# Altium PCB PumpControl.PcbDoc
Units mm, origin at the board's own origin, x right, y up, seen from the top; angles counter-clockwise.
Board outline 52.07 x 92.61 mm, 2 copper layers (Top Layer, Bottom Layer); 86 components, 56 nets, 282 pads, 79 vias.
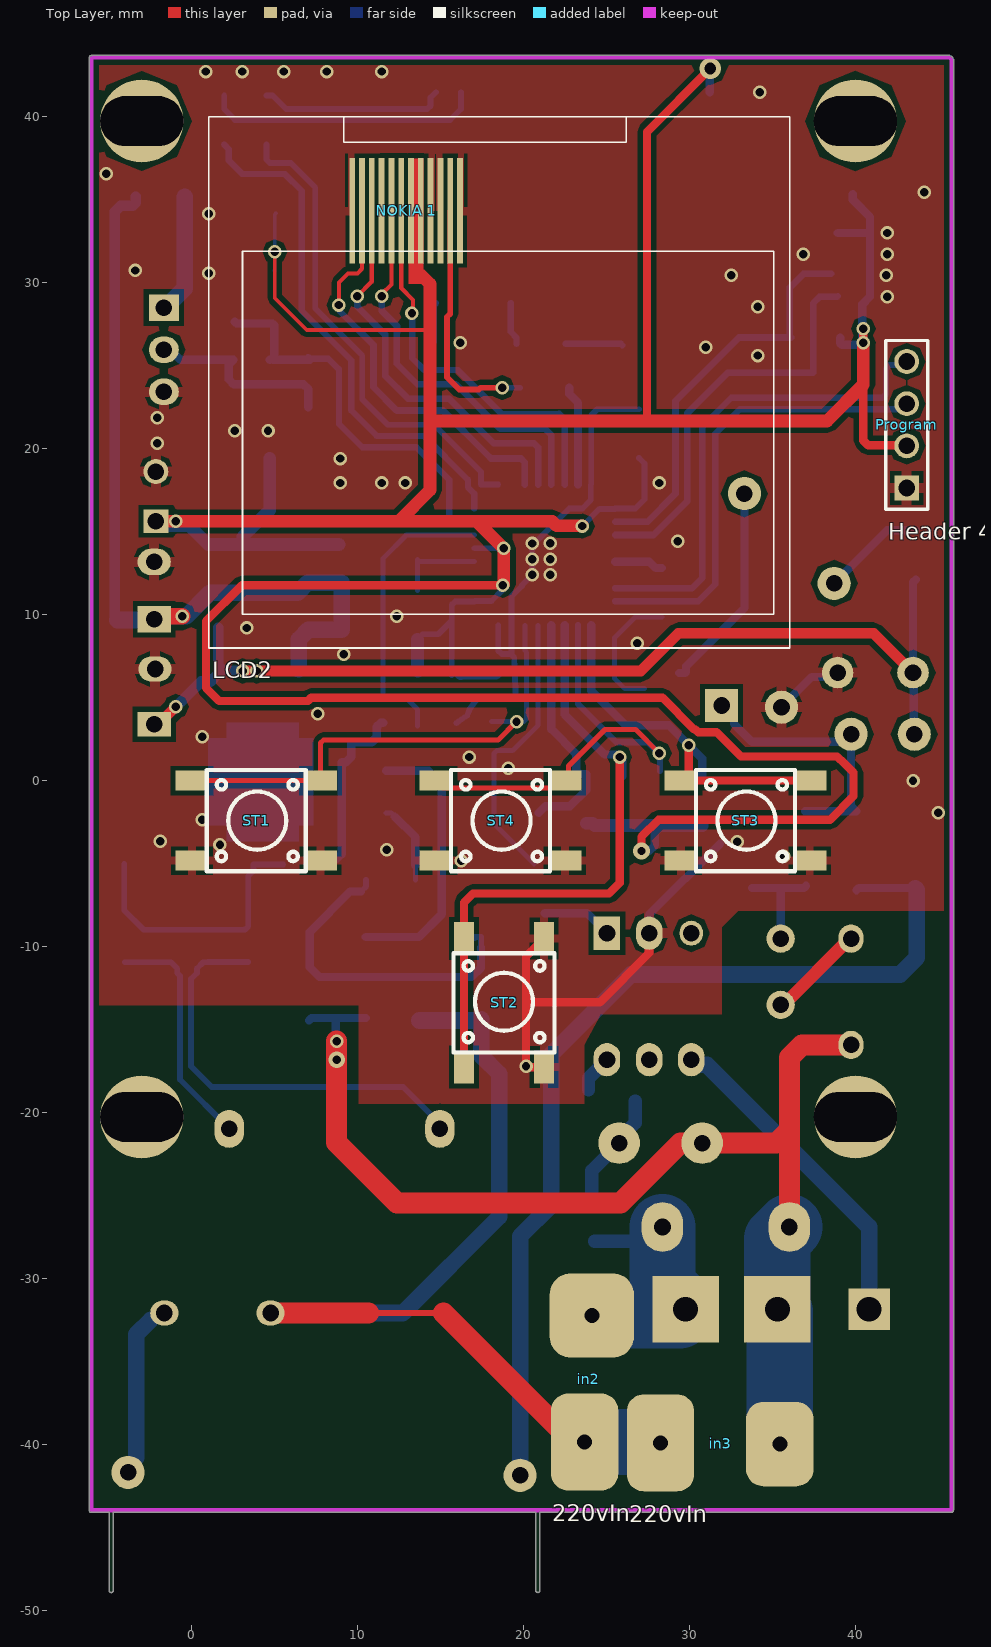
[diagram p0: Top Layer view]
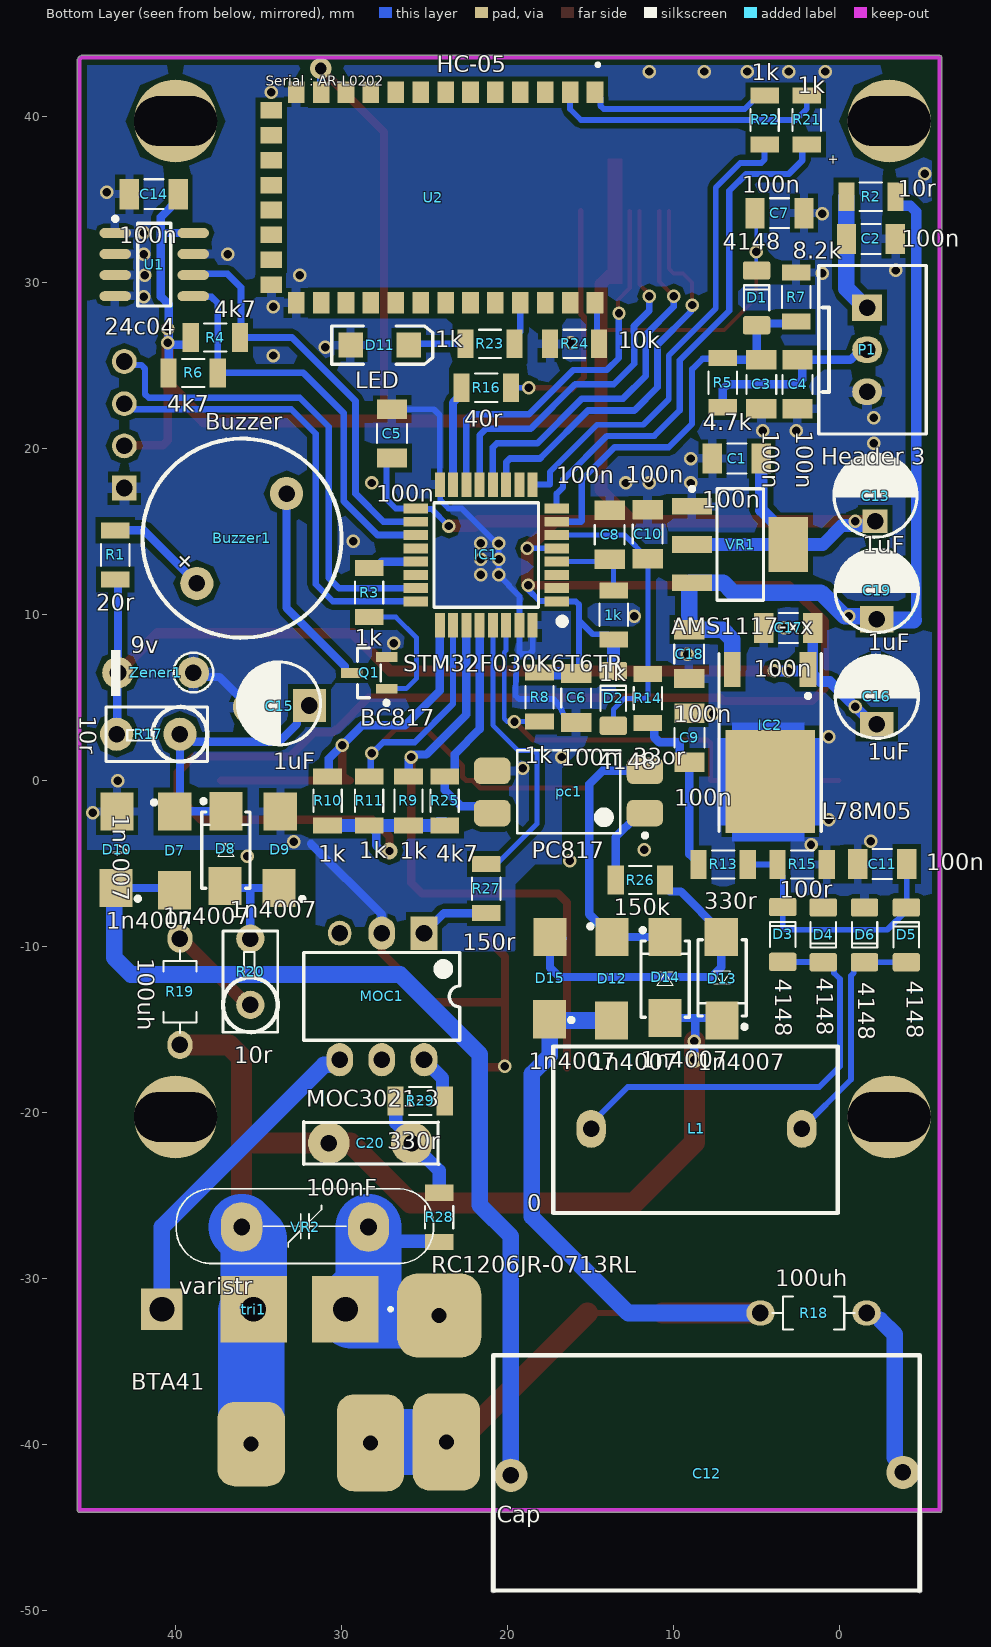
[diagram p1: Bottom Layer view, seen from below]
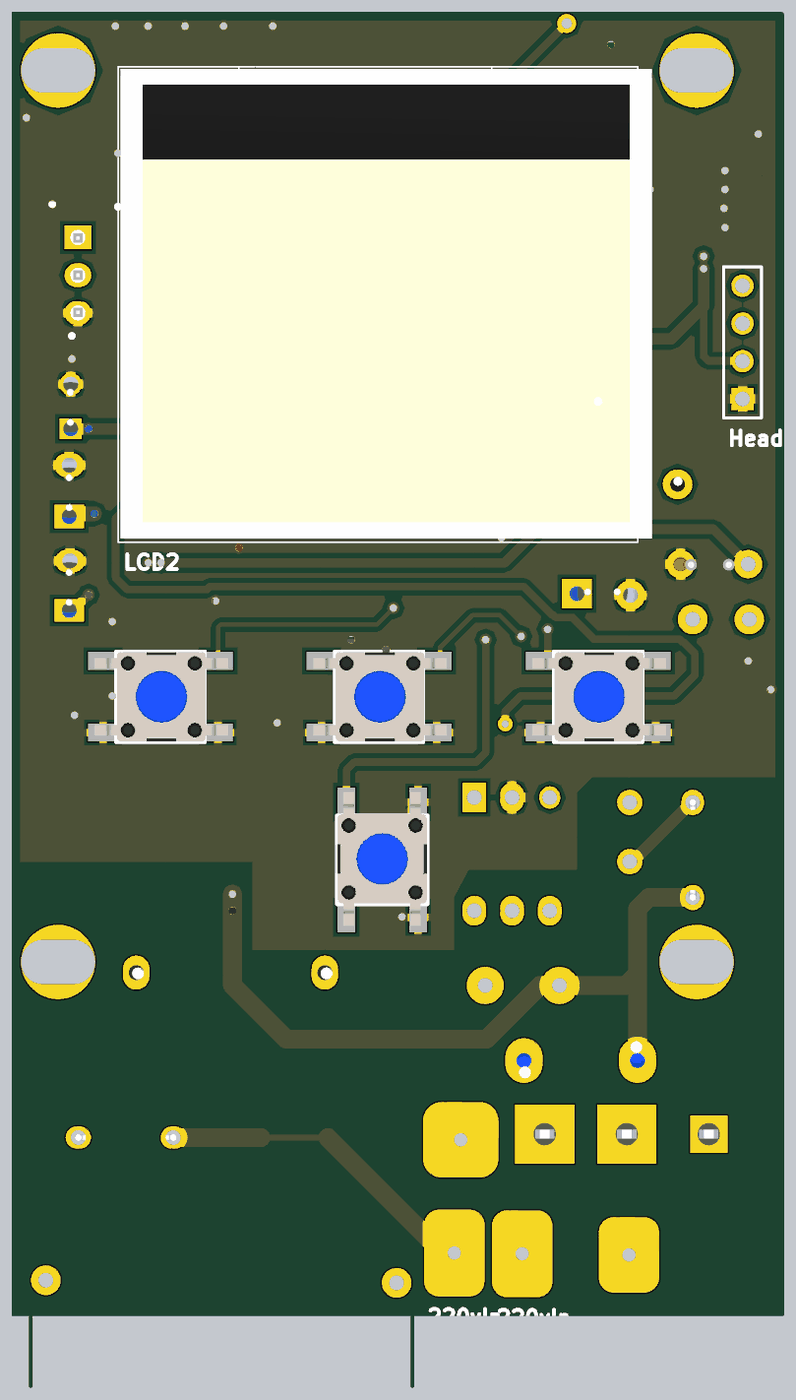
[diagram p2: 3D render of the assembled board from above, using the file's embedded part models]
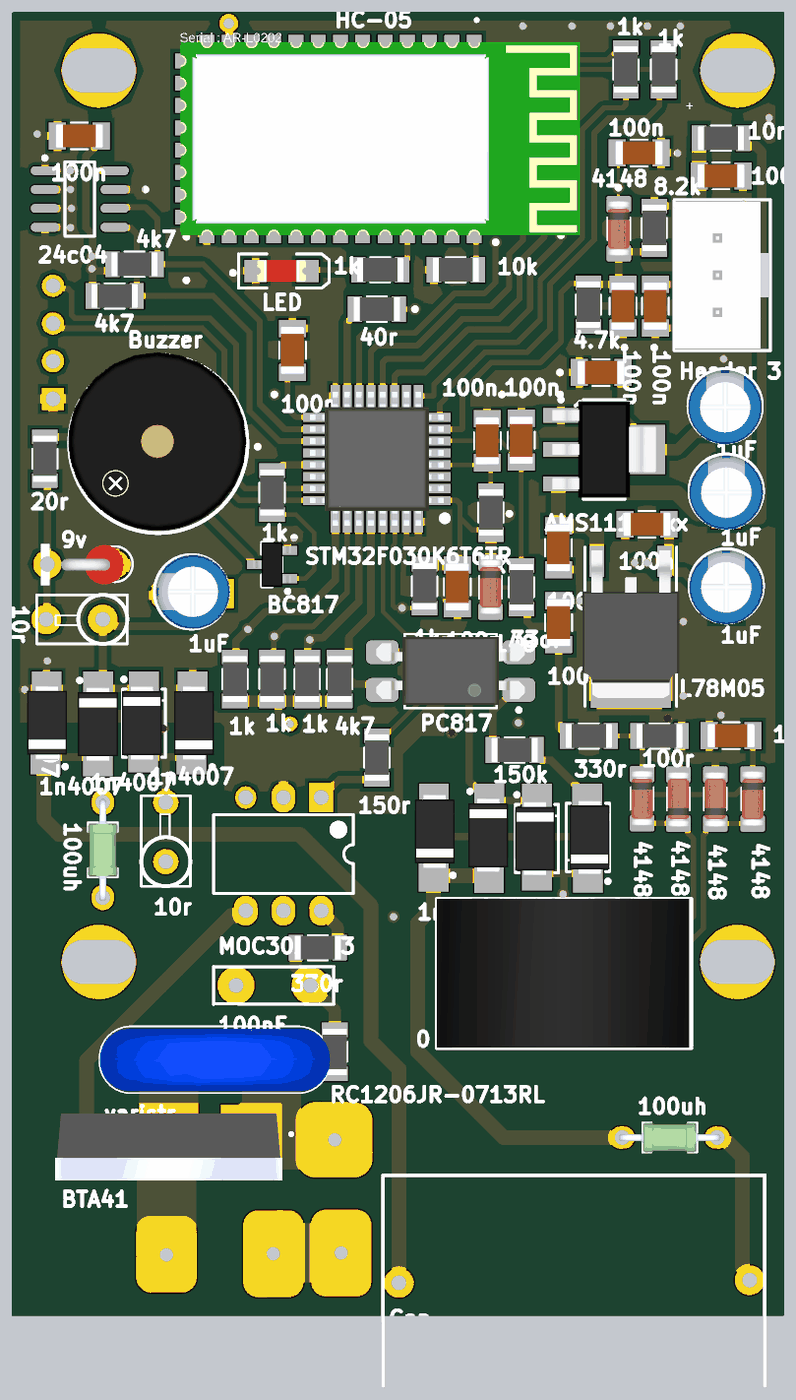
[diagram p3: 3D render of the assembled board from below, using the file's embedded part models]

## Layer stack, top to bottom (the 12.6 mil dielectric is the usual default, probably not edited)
Top Solder: solder mask 0.0102, Solder Resist, Dk 3.5
Top Layer: signal copper 0.0356
Dielectric 1: dielectric 0.32, FR-4, Dk 4.8
Bottom Layer: signal copper 0.0356
Bottom Solder: solder mask 0.0102, Solder Resist, Dk 3.5

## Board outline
-4.953,-48.793 -4.953,-44.095 -6.02,-44.095 cw(c-6.02,-43.967) -6.147,-43.967 -6.147,43.561 cw(c-6.02,43.561) -6.02,43.688 45.695,43.688 45.785,43.651 45.886,43.549 45.924,43.459 45.924,-43.967 cw(c45.796,-43.967) 45.796,-44.095 21.006,-44.095 21.006,-48.793 cw(c20.879,-48.793) 20.751,-48.793 20.751,-44.095 -4.699,-44.095 -4.699,-48.793 cw(c-4.826,-48.793)

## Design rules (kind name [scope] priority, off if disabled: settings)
Clearance Clearance_19 [InNamedPolygon('NONET_L-01_P-001') Or InNamedPolygon('NONET_L-01_P-001')] p1: gap=0.305 ignorepadtopadclearanceinfootprint=TRUE
Clearance Clearance_18 [InNamedPolygon('Top Layer-No Net')] p2: gap=0.4 ignorepadtopadclearanceinfootprint=FALSE
Clearance Clearance_17 [InNamedPolygon('Top Layer-No Net')] p3: gap=0.254 ignorepadtopadclearanceinfootprint=FALSE except(0: Arc-Hole Track-Hole SMDPad-Hole THPad-Hole Via-Hole Fill-Hole Poly-Hole Region-Hole Text-Hole)
Clearance Clearance_16 [InNamedPolygon('Top Layer-No Net')] p4: gap=0.4 ignorepadtopadclearanceinfootprint=FALSE
Clearance Clearance_15 [InNamedPolygon('GND_L02_P008')] p5: gap=0.3 ignorepadtopadclearanceinfootprint=TRUE
Clearance Clearance_14 [InNamedPolygon('GND_L01_P006')] p6: gap=0.381 ignorepadtopadclearanceinfootprint=TRUE
Clearance Clearance_13 [InNamedPolygon('GND_L01_P006')] p7: gap=0.381 ignorepadtopadclearanceinfootprint=TRUE
Clearance Clearance_12 [InNamedPolygon('GND_L01_P006')] p8: gap=0.2 ignorepadtopadclearanceinfootprint=FALSE
Clearance Clearance_11 [InNamedPolygon('GND_L01_P006')] p9: gap=0.254 ignorepadtopadclearanceinfootprint=FALSE except(0: Arc-Hole Track-Hole SMDPad-Hole THPad-Hole Via-Hole Fill-Hole Poly-Hole Region-Hole Text-Hole)
Clearance Clearance_10 [InNamedPolygon('GND_L02_P008')] p10: gap=0.5 ignorepadtopadclearanceinfootprint=FALSE
Clearance Clearance_9 [InNamedPolygon('GND_L01_P006')] p11: gap=0.5 ignorepadtopadclearanceinfootprint=FALSE
Clearance Clearance_8 [InNamedPolygon('GND_L01_P006')] p12: gap=0.254 ignorepadtopadclearanceinfootprint=FALSE except(0: Arc-Hole Track-Hole SMDPad-Hole THPad-Hole Via-Hole Fill-Hole Poly-Hole Region-Hole Text-Hole)
Clearance Clearance_7 [InNamedPolygon('GND_L01_P006')] p13: gap=0.5 ignorepadtopadclearanceinfootprint=FALSE
Clearance Clearance_6 [InNamedPolygon('GND_L01_P006')] p14: gap=0.254 ignorepadtopadclearanceinfootprint=FALSE except(0: Arc-Hole Track-Hole SMDPad-Hole THPad-Hole Via-Hole Fill-Hole Poly-Hole Region-Hole Text-Hole)
Clearance 0 [InNamedPolygon('GND_L01_P006')] p15: gap=0.254 ignorepadtopadclearanceinfootprint=FALSE except(0: Arc-Hole Track-Hole SMDPad-Hole THPad-Hole Via-Hole Fill-Hole Poly-Hole Region-Hole Text-Hole)
Clearance Clearance_5 [InNamedPolygon('GND_L01_P006')] p16: gap=0.254 ignorepadtopadclearanceinfootprint=FALSE except(0: Arc-Hole Track-Hole SMDPad-Hole THPad-Hole Via-Hole Fill-Hole Poly-Hole Region-Hole Text-Hole)
Clearance Clearance_4 [InNamedPolygon('GND-E_L02_P002')] p17: gap=0.508 ignorepadtopadclearanceinfootprint=FALSE
Clearance Clearance_3 [InNamedPolygon('GND_L01_P001')] p18: gap=0.635 ignorepadtopadclearanceinfootprint=FALSE
Clearance Clearance_2 [InNamedPolygon('GND_L02_P000')] p19: gap=0.508 ignorepadtopadclearanceinfootprint=FALSE
Clearance Clearance_1 [InNamedPolygon('Bottom Layer-GND')] p20: gap=0.356 ignorepadtopadclearanceinfootprint=FALSE
Clearance [All] p21: gap=0.3 ignorepadtopadclearanceinfootprint=FALSE
PolygonConnect PolygonConnect_15 [All vs IsNamedPolygon('NONET_L-01_P-001') Or IsNamedPolygon('NONET_L-01_P-001')] p1: thpad.connectstyle=Relief thpad.reliefconductorwidth=0.635 thpad.reliefentries=4 thpad.polygonreliefangle="90 Angle" thpad.airgapwidth=0.254 smdpad.connectstyle=Relief smdpad.reliefconductorwidth=0.508 smdpad.reliefentries=4 smdpad.polygonreliefangle="90 Angle" smdpad.airgapwidth=0.254 via.connectstyle=Direct via.reliefconductorwidth=0.254 via.reliefentries=4 via.polygonreliefangle="90 Angle" via.airgapwidth=0.254
PolygonConnect PolygonConnect_14 [All vs IsNamedPolygon('GND_L02_P008')] p2: thpad.connectstyle=Relief thpad.reliefconductorwidth=0.762 thpad.reliefentries=4 thpad.polygonreliefangle="90 Angle" thpad.airgapwidth=0.3 smdpad.connectstyle=Relief smdpad.reliefconductorwidth=0.508 smdpad.reliefentries=4 smdpad.polygonreliefangle="90 Angle" smdpad.airgapwidth=0.3 via.connectstyle=Relief via.reliefconductorwidth=0.254 via.reliefentries=4 via.polygonreliefangle="90 Angle" via.airgapwidth=0.3
PolygonConnect PolygonConnect_13 [All vs IsNamedPolygon('GND_L01_P006')] p3: thpad.connectstyle=Relief thpad.reliefconductorwidth=0.889 thpad.reliefentries=4 thpad.polygonreliefangle="90 Angle" thpad.airgapwidth=0.254 smdpad.connectstyle=Relief smdpad.reliefconductorwidth=0.635 smdpad.reliefentries=4 smdpad.polygonreliefangle="90 Angle" smdpad.airgapwidth=0.254 via.connectstyle=Direct via.reliefconductorwidth=0.254 via.reliefentries=4 via.polygonreliefangle="90 Angle" via.airgapwidth=0.254
PolygonConnect PolygonConnect_12 [All vs IsNamedPolygon('GND_L01_P006')] p4: thpad.connectstyle=Relief thpad.reliefconductorwidth=0.889 thpad.reliefentries=4 thpad.polygonreliefangle="90 Angle" thpad.airgapwidth=0.254 smdpad.connectstyle=Relief smdpad.reliefconductorwidth=0.508 smdpad.reliefentries=4 smdpad.polygonreliefangle="90 Angle" smdpad.airgapwidth=0.254 via.connectstyle=Direct via.reliefconductorwidth=0.254 via.reliefentries=4 via.polygonreliefangle="90 Angle" via.airgapwidth=0.254
PolygonConnect PolygonConnect_11 [All vs IsNamedPolygon('GND_L01_P006')] p5: thpad.connectstyle=Relief thpad.reliefconductorwidth=0.508 thpad.reliefentries=4 thpad.polygonreliefangle="90 Angle" thpad.airgapwidth=0.254 smdpad.connectstyle=Relief smdpad.reliefconductorwidth=0.508 smdpad.reliefentries=4 smdpad.polygonreliefangle="90 Angle" smdpad.airgapwidth=0.254 via.connectstyle=Direct via.reliefconductorwidth=0.254 via.reliefentries=4 via.polygonreliefangle="90 Angle" via.airgapwidth=0.254
PolygonConnect PolygonConnect_10 [All vs IsNamedPolygon('GND_L01_P006')] p6: thpad.connectstyle=Relief thpad.reliefconductorwidth=0.254 thpad.reliefentries=4 thpad.polygonreliefangle="90 Angle" thpad.airgapwidth=0.254 smdpad.connectstyle=Relief smdpad.reliefconductorwidth=0.254 smdpad.reliefentries=4 smdpad.polygonreliefangle="90 Angle" smdpad.airgapwidth=0.254 via.connectstyle=Direct via.reliefconductorwidth=0.254 via.reliefentries=4 via.polygonreliefangle="90 Angle" via.airgapwidth=0.254
PolygonConnect PolygonConnect_9 [All vs IsNamedPolygon('GND_L01_P006')] p7: thpad.connectstyle=Direct thpad.reliefconductorwidth=0.254 thpad.reliefentries=4 thpad.polygonreliefangle="90 Angle" thpad.airgapwidth=0.254 smdpad.connectstyle=Relief smdpad.reliefconductorwidth=0.254 smdpad.reliefentries=4 smdpad.polygonreliefangle="90 Angle" smdpad.airgapwidth=0.254 via.connectstyle=Relief via.reliefconductorwidth=0.254 via.reliefentries=4 via.polygonreliefangle="90 Angle" via.airgapwidth=0.254
PolygonConnect PolygonConnect_8 [All vs IsNamedPolygon('GND_L01_P006')] p8: connectstyle=Relief reliefconductorwidth=0.254 reliefentries=4 polygonreliefangle="90 Angle" airgapwidth=0.254
PolygonConnect PolygonConnect_7 [All vs IsNamedPolygon('GND_L02_P008')] p9: connectstyle=Relief reliefconductorwidth=0.254 reliefentries=4 polygonreliefangle="90 Angle" airgapwidth=0.254
PolygonConnect PolygonConnect_6 [All vs IsNamedPolygon('GND_L02_P008')] p10: connectstyle=Direct reliefconductorwidth=0.254 reliefentries=4 polygonreliefangle="90 Angle" airgapwidth=0.254
PolygonConnect PolygonConnect_5 [All vs IsNamedPolygon('GND_L02_P008')] p11: thpad.connectstyle=Direct thpad.reliefconductorwidth=0.254 thpad.reliefentries=4 thpad.polygonreliefangle="90 Angle" thpad.airgapwidth=0.254 smdpad.connectstyle=Relief smdpad.reliefconductorwidth=0.254 smdpad.reliefentries=4 smdpad.polygonreliefangle="90 Angle" smdpad.airgapwidth=0.254 via.connectstyle=Relief via.reliefconductorwidth=0.254 via.reliefentries=4 via.polygonreliefangle="90 Angle" via.airgapwidth=0.254
PolygonConnect PolygonConnect_4 [All vs IsNamedPolygon('GND-E_L02_P002')] p12: thpad.connectstyle=Relief thpad.reliefconductorwidth=0.635 thpad.reliefentries=4 thpad.polygonreliefangle="90 Angle" thpad.airgapwidth=0.254 smdpad.connectstyle=Relief smdpad.reliefconductorwidth=0.381 smdpad.reliefentries=4 smdpad.polygonreliefangle="90 Angle" smdpad.airgapwidth=0.254 via.connectstyle=Direct via.reliefconductorwidth=0.254 via.reliefentries=4 via.polygonreliefangle="90 Angle" via.airgapwidth=0.254
PolygonConnect PolygonConnect_3 [All vs IsNamedPolygon('GND_L01_P001')] p13: thpad.connectstyle=Relief thpad.reliefconductorwidth=0.635 thpad.reliefentries=4 thpad.polygonreliefangle="90 Angle" thpad.airgapwidth=0.254 smdpad.connectstyle=Relief smdpad.reliefconductorwidth=0.635 smdpad.reliefentries=4 smdpad.polygonreliefangle="90 Angle" smdpad.airgapwidth=0.254 via.connectstyle=Direct via.reliefconductorwidth=0.254 via.reliefentries=4 via.polygonreliefangle="90 Angle" via.airgapwidth=0.254
PolygonConnect PolygonConnect_2 [All vs IsNamedPolygon('GND_L02_P000')] p14: thpad.connectstyle=Relief thpad.reliefconductorwidth=0.635 thpad.reliefentries=4 thpad.polygonreliefangle="90 Angle" thpad.airgapwidth=0.254 smdpad.connectstyle=Relief smdpad.reliefconductorwidth=0.254 smdpad.reliefentries=4 smdpad.polygonreliefangle="90 Angle" smdpad.airgapwidth=0.381 via.connectstyle=Direct via.reliefconductorwidth=0.254 via.reliefentries=4 via.polygonreliefangle="90 Angle" via.airgapwidth=0.254
PolygonConnect PolygonConnect_1 [All vs IsNamedPolygon('Bottom Layer-GND')] p15: thpad.connectstyle=Relief thpad.reliefconductorwidth=0.635 thpad.reliefentries=4 thpad.polygonreliefangle="90 Angle" thpad.airgapwidth=0.254 smdpad.connectstyle=Relief smdpad.reliefconductorwidth=0.381 smdpad.reliefentries=4 smdpad.polygonreliefangle="90 Angle" smdpad.airgapwidth=0.254 via.connectstyle=Direct via.reliefconductorwidth=0.254 via.reliefentries=4 via.polygonreliefangle="90 Angle" via.airgapwidth=0.254
PolygonConnect [All] p16: connectstyle=Direct reliefconductorwidth=0 reliefentries=2 polygonreliefangle="90 Angle" airgapwidth=0
RoutingVias [All] p1: holewidth=0.5 width=1 viastyle="Through Hole" minholewidth=0.5 minwidth=1 maxholewidth=0.5 maxwidth=1
SolderMaskExpansion [All] p1: expansion=0.102
Width [All] p1: maxlimit=4 minlimit=0.229 preferedwidth=0.5
30 further rules are at their usual default settings.

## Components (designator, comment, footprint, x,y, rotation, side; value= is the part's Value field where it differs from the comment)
1k "1k" RESC3116X65N 13.614,9.982 r270 bottom
Buzzer1 "Buzzer" BUZZER 36.07,14.416 r45 bottom
C1 "100n" CAPC3216X88N 6.198,19.406 r180 bottom
C2 "100n" CAPC3216X88N -1.88,32.639 r180 bottom
C3 "100n" CAPC3216X88N 4.723,23.876 r90 bottom
C4 "100n" CAPC3216X88N 2.54,23.876 r90 bottom
C5 "100n" CAPC3216X88N 26.975,20.904 r270 bottom
C6 "100n" CAPC3216X88N 15.875,4.978 r90 bottom
C7 "100n" CAPC3216X88N 3.632,34.188 r0 bottom
C8 "100n" CAPC3216X88N 13.855,14.811 r270 bottom
C9 "100n" CAPC3216X88N 9.053,2.58 r270 bottom
C10 "100n" CAPC3216X88N 11.57,14.847 r270 bottom
C11 "100n" CAPC3216X88N -2.565,-5.029 r180 bottom
C12 "Cap" RAD-0.3 8.661,-44.475 r0 bottom value=1.5uf
C13 "1uF" "Cap electrolitic radial 5x11-2"#1 -2.159,17.069 r90 bottom
C14 "100n" CAPC3216X88N 41.326,35.331 r180 bottom
C15 "1uF" "Cap electrolitic radial 5x11-2"#2 33.68,4.648 r0 bottom
C16 "1uF" "Cap electrolitic radial 5x11-2"#3 -2.235,4.953 r90 bottom
C17 "100n" CAPC3216X88N 3.094,9.195 r180 bottom
C18 "100n" CAPC3216X88N 9.068,7.62 r90 bottom
C19 "1uF" "Cap electrolitic radial 5x11-2"#4 -2.235,11.328 r90 bottom
C20 "100nF" "Cap 10nF" 25.781,-21.844 r0 bottom
D1 "4148" "SOD80, LL-34" 5.004,29.083 r270 bottom
D2 "4148" "SOD80, LL-34" 13.638,4.953 r270 bottom
D3 "4148" "SOD80, LL-34" 3.429,-9.271 r270 bottom
D4 "4148" "SOD80, LL-34" 0.991,-9.296 r90 bottom
D5 "4148" "SOD80, LL-34" -4.013,-9.296 r270 bottom
D6 "4148" "SOD80, LL-34" -1.499,-9.296 r90 bottom
D7 "1n4007" DIOM4629X24N#1 39.957,-4.267 r90 bottom
D8 "1n4007" DIOM4629X24N#2 36.982,-4.191 r90 bottom
D9 "1n4007" DIOM4629X24N#3 33.73,-4.184 r270 bottom
D10 "1n4007" DIOM4629X24N#4 43.636,-4.166 r270 bottom
D11 "LED" "LED 1206" 27.711,26.238 r180 bottom
D12 "1n4007" DIOM4629X24N#5 13.67,-11.734 r90 bottom
D13 "1n4007" DIOM4629X24N#6 7.087,-11.886 r270 bottom
D14 "1n4007" DIOM4629X24N#7 10.517,-11.962 r90 bottom
D15 "1n4007" DIOM4629X24N#8 17.527,-11.481 r270 bottom
IC1 "STM32F030K6T6TR" QFP80P900X900X160-32N 21.295,13.596 r0 bottom
IC2 "L78M05" TO-252 4.191,3.327 r0 bottom
in2 "220vIn" HDR1X2#1 26.06,-40.513 r0 top
in3 "220vIn" HDR1X2#2 34.722,-40.716 r180 top
L1 "0" ZMC 8.755,-20.98 r180 bottom value=300uH
MOC1 "MOC3021-3" DIP-6 27.584,-13.005 r270 bottom
"NOKIA 1" "LCD2" "LCD NOKIA 1202" 18.732,23.98 r0 top
P1 "Header 3" 3PIN -1.651,25.959 r270 bottom
pc1 "PC817" "SMT Gullwing Lead-Form" 16.332,-0.686 r0 bottom
Program "Header 4" HDR1X4 43.104,17.628 r90 top
Q1 "BC817" SOT23_N 28.352,6.484 r0 bottom
R1 "20r" RESC3116X65N 43.65,13.596 r90 bottom
R2 "10r" RESC3116X65N -1.88,35.179 r0 bottom
R3 "1k" RESC3116X65N 28.352,11.328 r270 bottom
R4 "4k7" RESC3116X65N 37.617,26.694 r180 bottom
R5 "4.7k" RESC3116X65N 7.047,23.975 r90 bottom
R6 "4k7" RESC3116X65N 38.95,24.562 r180 bottom
R7 "8.2k" RESC3116X65N 2.616,29.134 r270 bottom
R8 "1k" RESC3116X65N 18.085,5.029 r90 bottom
R9 "1k" RESC3116X65N 25.984,-1.222 r270 bottom
R10 "1k" RESC3116X65N 30.854,-1.222 r270 bottom
R11 "1k" RESC3116X65N 28.352,-1.222 r270 bottom
R13 "330r" RESC3116X65N 7.017,-5.055 r180 bottom
R14 "33or" RESC3116X65N 11.557,4.953 r270 bottom
R15 "100r" RESC3116X65N 2.261,-5.055 r0 bottom
R16 "40r" RESC3116X65N 21.295,23.672 r180 bottom
R17 "10r" RES-(1/2)-Stand#1 39.751,2.794 r0 bottom
R18 "100uh" RESAD640W45L370D200 1.575,-32.08 r180 bottom
R19 "100uh" RESAD640W45L370D200 39.751,-12.725 r90 bottom
R20 "10r" RES-(1/2)-Stand#2 35.509,-13.513 r90 bottom
R21 "1k" RESC3116X65N 1.981,39.802 r270 bottom
R22 "1k" RESC3116X65N 4.521,39.802 r270 bottom
R23 "1k" RESC3116X65N 21.07,26.314 r180 bottom
R24 "10k" RESC3116X65N 15.977,26.314 r180 bottom
R25 "4k7" RESC3116X65N 23.8,-1.222 r270 bottom
R26 "150k" RESC3116X65N 12.014,-5.994 r180 bottom
R27 "150r" RESC3116X65N 21.295,-6.509 r90 bottom
R28 "RC1206JR-0713RL" RESC3116X65N 24.13,-26.314 r270 bottom
R29 "330r" RESC3116X65N 25.273,-19.304 r180 bottom
ST1 "SW-PB" "PUSH BOTTOM 6*6" 3.974,-2.286 r90 top
ST2 "SW-PB" "PUSH BOTTOM 6*6" 18.716,-13.327 r180 top
ST3 "SW-PB" "PUSH BOTTOM 6*6" 33.451,-2.286 r90 top
ST4 "SW-PB" "PUSH BOTTOM 6*6" 18.694,-2.286 r90 top
tri1 "BTA41" TO552P1530X450X2110-3B 35.311,-31.852 r0 bottom
U1 "24c04" SO8_L 41.3,31.09 r180 bottom
U2 "HC-05" XCVR_HC-05 21.07,35.128 r270 bottom
VR1 "AMS1117-xx" SOT-223 5.994,14.224 r0 bottom
VR2 "varistr" "14D XXX" 32.225,-26.848 r180 bottom value=xxDxxx
Zener1 "9v" "Diode 1W_Stand" 40.919,6.484 r0 bottom

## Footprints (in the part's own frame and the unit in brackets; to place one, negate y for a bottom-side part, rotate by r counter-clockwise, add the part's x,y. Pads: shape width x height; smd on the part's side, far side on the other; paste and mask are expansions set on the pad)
3PIN [mm]
  rect 1.6x1.8 hole 1: 1(-2.54,0)
  oval 1.6x1.8 hole 1: 2(0,0) 3(2.54,0)
  silkscreen extent -5.08,-2.92 5.08,3.56, body extent -4.95,-2.9 4.95,3.49, height 7
"14D XXX" [mm] "MOV-14DxxxK Metal Oxide Varistors (MOVs) are 14 mm-Design:Abbas Basereh"
  oval 2.5x3 hole 1: 1(3.836,-0.051) 2(-3.81,-0.051)
  silkscreen extent -7.75,-2.25 7.75,2.25, body extent -7.73,-2.1 7.77,2.1, height 19.5
BUZZER [mm]
  round 2 hole 1: 1(0.092,3.675) 2(0.092,-3.975)
  silkscreen extent -5.91,-6.17 6.09,5.82, body extent -5.75,-6.25 6.25,5.75, height 9.5
"Cap 10nF" [mm]
  round 2.5 hole 1: 1(0,0) 2(5,0)
  silkscreen extent -1.62,-1.28 6.51,1.29
"Cap electrolitic radial 5x11-2"#1 [mm] "Cap electrolitic radial 5x11-2-Design:Abbas Basereh"
  rect 1.4x1.5 hole 1: 1(-1.448,0.025)
  round 1.5 hole 1: 2(1.549,0.025)
  silkscreen extent -2.4,-2.5 2.6,2.5, body extent -2.5,-2.5 2.5,2.5, height 11.3
"Cap electrolitic radial 5x11-2"#2 [mm] "Cap electrolitic radial 5x11-2-Design:Abbas Basereh"
  rect 2x2 hole 1: 1(-1.727,0.127)
  round 2 hole 1: 2(1.88,0.229)
  silkscreen extent -2.4,-2.5 2.6,2.5, body extent -2.5,-2.5 2.5,2.5, height 11.3
"Cap electrolitic radial 5x11-2"#3 [mm] "Cap electrolitic radial 5x11-2-Design:Abbas Basereh"
  rect 1.5x2 hole 1: 1(-1.559,0)
  oval 1.5x2 hole 1: 2(1.769,0.051)
  silkscreen extent -2.4,-2.5 2.6,2.5, body extent -2.5,-2.5 2.5,2.5, height 11.3
"Cap electrolitic radial 5x11-2"#4 [mm] "Cap electrolitic radial 5x11-2-Design:Abbas Basereh"
  rect 1.6x2 hole 1: 1(-1.61,0)
  oval 1.6x2 hole 1: 2(1.845,0)
  silkscreen extent -2.4,-2.5 2.6,2.5, body extent -2.5,-2.5 2.5,2.5, height 11.3
CAPC3216X88N [mm]
  rect 1.16x1.82 smd: 1(-1.475,0) 2(1.475,0)
  silkscreen extent -0.57,-0.9 0.57,0.9, body extent -1.6,-0.8 1.6,0.8, height 0.88
"Diode 1W_Stand" [mil]
  round 75 hole 39.37: 1(-78,-1) 2(101,-1)
  silkscreen extent -125,-55 118,55, body extent -103,-52 65,53, height 291
DIOM4629X24N#1 [mm] "Molded Diode, 2-Leads, Body 4/60x2/90mm, IPC Medium Density-Design:Abbas Basereh"
  rect 2.3x2 smd: 1(-2.337,0.127) 2(2.413,0.102)
  silkscreen extent 2.83,1.23 3.07,1.48, body extent -2.5,-1.22 2.5,1.48, height 2.2
DIOM4629X24N#2 [mm] "Molded Diode, 2-Leads, Body 4/60x2/90mm, IPC Medium Density-Design:Abbas Basereh"
  rect 2.3x2 smd: 1(-2.152,0.05) 2(2.344,-0.001)
  silkscreen extent -2.3,-1.45 3.07,1.48, body extent -2.5,-1.22 2.5,1.48, height 2.2
DIOM4629X24N#3 [mm] "Molded Diode, 2-Leads, Body 4/60x2/90mm, IPC Medium Density-Design:Abbas Basereh"
  rect 2.3x2 smd: 1(-2.33,0.025) 2(2.286,-0.051)
  silkscreen extent 2.83,1.22 3.07,1.47, body extent -2.5,-1.22 2.5,1.48, height 2.2
DIOM4629X24N#4 [mm] "Molded Diode, 2-Leads, Body 4/60x2/90mm, IPC Medium Density-Design:Abbas Basereh"
  rect 2.3x2 smd: 1(-2.297,0.102) 2(2.311,0.025)
  silkscreen extent 2.83,1.22 3.07,1.47, body extent -2.5,-1.22 2.5,1.48, height 2.2
DIOM4629X24N#5 [mm] "Molded Diode, 2-Leads, Body 4/60x2/90mm, IPC Medium Density-Design:Abbas Basereh"
  rect 2.3x2 smd: 1(-2.722,0.076) 2(2.311,0.051)
  silkscreen extent 2.83,1.23 3.07,1.48, body extent -2.5,-1.22 2.5,1.48, height 2.2
DIOM4629X24N#6 [mm] "Molded Diode, 2-Leads, Body 4/60x2/90mm, IPC Medium Density-Design:Abbas Basereh"
  rect 2.3x2 smd: 1(-2.464,-0.051) 2(2.565,0)
  silkscreen extent -2.3,-1.45 3.07,1.47, body extent -2.5,-1.22 2.5,1.48, height 2.2
DIOM4629X24N#7 [mm] "Molded Diode, 2-Leads, Body 4/60x2/90mm, IPC Medium Density-Design:Abbas Basereh"
  rect 2.3x2 smd: 1(-2.337,0) 2(2.54,0)
  silkscreen extent -2.3,-1.45 3.07,1.48, body extent -2.5,-1.22 2.5,1.48, height 2.2
DIOM4629X24N#8 [mm] "Molded Diode, 2-Leads, Body 4/60x2/90mm, IPC Medium Density-Design:Abbas Basereh"
  rect 2.3x2 smd: 1(-2.058,0.076) 2(2.896,0.051)
  silkscreen extent 2.83,1.22 3.07,1.47, body extent -2.5,-1.22 2.5,1.48, height 2.2
DIP-6 [mm] "DIP; 6 Leads; Row Spacing 7.62 mm; Pitch 2.54 mm"
  rect 2x1.6 hole 1: 1(-3.81,2.54)
  oval 2x1.6 hole 1: 2(-3.81,0) 4(3.81,-2.54) 5(3.81,0) 6(3.81,2.54)
  oval 1.5x1.4 hole 1: 3(-3.81,-2.54)
  silkscreen extent -2.65,-4.7 2.65,4.7
HDR1X2#1 [mil] "Connector; Header; 2 Position"
  rrect50% 160x230 hole 35.43: 1(-93,26)
  rrect50% 200x200 hole 35.43: 2(-76,326)
HDR1X2#2 [mil] "Connector; Header; 2 Position"
  rrect50% 160x200 hole 35.43: 1(-29,-29)
  rrect50% 160x230 hole 35.43: 2(254,-32)
HDR1X4 [mm] "Connector; Header; 4 Position"
  rect 1.5x1.5 hole 1: 1(0,0)
  round 1.5 hole 1: 2(2.54,0) 3(5.08,0) 4(7.62,0)
  silkscreen extent -1.27,-1.27 8.89,1.27
"LCD NOKIA 1202" [mm]
  rect 0.35x6.35 smd: 1(-9.039,10.344) 2(-8.448,10.344) 3(-7.857,10.344) 4(-7.267,10.344) 5(-6.676,10.344) 6(-6.085,10.344) 7(-5.494,10.344) 8(-4.903,10.344) 9(-4.312,10.344) 10(-3.721,10.344) 11(-3.13,10.344) 12(-2.539,10.344)
  silkscreen extent -17.68,-15.99 17.32,16.01, body extent -17.52,-15.75 18.28,15.85, height 2.51
"LED 1206" [mm]
  rect 1.5x1.5 smd: 1(-1.75,0) 2(1.75,0)
  silkscreen extent -2.9,-1.15 3.2,1.15, body extent -1.65,-0.72 1.65,0.73, height 1.36
"PUSH BOTTOM 6*6" [mm]
  rect 1.2x2 smd: 1(-2.54,3.937) 1(-2.54,-3.81) 2(2.286,-3.81) 2(2.286,3.937)
  silkscreen extent -3.18,-2.92 2.92,3.05, body extent -3.13,-4.5 2.87,4.5, height 4.2
QFP80P900X900X160-32N [mm] "Integrated Circuit"
  rect 1.475x0.6 smd: 1(-4.238,2.8) 2(-4.238,2) 3(-4.238,1.2) 4(-4.238,0.4) 5(-4.238,-0.4) 6(-4.238,-1.2) 7(-4.238,-2) 8(-4.238,-2.8) 17(4.238,-2.8) 18(4.238,-2) 19(4.238,-1.2) 20(4.238,-0.4) 21(4.238,0.4) 22(4.238,1.2) 23(4.238,2) 24(4.238,2.8)
  rect 0.6x1.475 smd: 9(-2.8,-4.238) 10(-2,-4.238) 11(-1.2,-4.238) 12(-0.4,-4.238) 13(0.4,-4.238) 14(1.2,-4.238) 15(2,-4.238) 16(2.8,-4.238) 25(2.8,4.238) 26(2,4.238) 27(1.2,4.238) 28(0.4,4.238) 29(-0.4,4.238) 30(-1.2,4.238) 31(-2,4.238) 32(-2.8,4.238)
  silkscreen extent -4.77,-3.15 3.15,4.2, body extent -4.5,-4.5 4.5,4.5, height 1.6
RAD-0.3 [mm] "Radial Cap, Thru-Hole; 2 Leads; 0.3 in Pin Spacing"
  round 2 hole 1: 1(-12.471,-2.794) 2(11.151,-2.616)
RES-(1/2)-Stand#1 [mm]
  round 2 hole 1: 1(0,0) 2(3.81,0)
  silkscreen extent -1.65,-1.65 4.44,1.65, body extent -1.68,-1.67 4.14,1.67, height 11
RES-(1/2)-Stand#2 [mm]
  round 1.7 hole 1: 1(0,0) 2(3.988,0)
  silkscreen extent -1.65,-1.65 4.44,1.65, body extent -1.68,-1.67 4.14,1.67, height 11
RESAD640W45L370D200 [mm]
  oval 1.7x1.5 hole 1: 1(-3.2,0) 2(3.2,0)
  silkscreen extent -2.47,-1 2.47,1, body extent -3.42,-1 3.42,1, height 2
RESC3116X65N [mm]
  rect 0.97x1.73 smd: 1(-1.48,0) 2(1.48,0)
  silkscreen extent -0.67,-0.85 0.67,0.85, body extent -1.55,-0.8 1.55,0.8, height 0.65
"SMT Gullwing Lead-Form" [mm] "SOP, 4-Leads, Body 4/65x6/75mm, Pitch 2/54mm, IPC Medium Density designer:abbas basereh"
  rrect50% 2.2x1.6 smd mask+0.06: 1(-4.6,1.27) 2(-4.6,-1.27) 3(4.6,-1.27) 4(4.6,1.27)
  silkscreen extent -4.72,-2.5 3.1,2.74, body extent -5,-2.29 5,2.29, height 3.89
SO8_L [mm] "SOIC, 8-Leads, Body 4.9x3.9mm, Pitch 1.27mm, IPC High Density"
  oval 1.9x0.6 smd: 1(-2.35,1.905) 2(-2.35,0.635) 3(-2.35,-0.635) 4(-2.35,-1.905) 5(2.35,-1.905) 6(2.35,-0.635) 7(2.35,0.635) 8(2.35,1.905)
  silkscreen extent -2.47,-2.5 1,2.88, body extent -2,-2.5 2,2.5, height 1.75
"SOD80, LL-34" [mm] "Diode, MiniMELF"
  round 0.5 on Mech15: 0(0,0)
  rrect25% 1.1x1.65 smd: 1(1.65,0) 2(-1.65,0)
  silkscreen extent -0.76,-0.76 0.76,0.76, body extent -1.88,-0.8 1.82,0.8, height 1.6
SOT23_N [mm] "SOT23, 3-Leads, Body 2.9x1.3mm, Pitch 0.95mm, Lead Span 2.3mm, IPC Medium Density"
  rect 1.3x0.6 smd: 1(-1.05,0.95) 2(-1.05,-0.95) 3(1.05,0)
  silkscreen extent -1.17,-1.5 0.7,1.92, body extent -1.27,-1.5 1.27,1.5, height 1.1
SOT-223 [mm]
  rect 2.4x1 smd: 1(2.9,-2.3) 2(2.9,0) 3(2.9,2.3)
  rect 2.4x3.3 smd: 4(-2.9,0)
  silkscreen extent -1.4,-3.47 3.03,3.35, body extent -3.49,-3.24 3.49,3.24, height 1.64
TO552P1530X450X2110-3B [mm]
  rect 4x4 hole 1.5: 1(-5.525,0) 2(0,0)
  rect 2.5x2.5 hole 1.5: 3(5.525,0)
  silkscreen extent -8.35,-0.1 -8.15,0.1, body extent -7.65,-1.4 7.65,3.1, height 21.1
TO-252 [mm] "D-PAK/TO-252-AA; 3 Leads (1 Cropped); Body 10.1 (inc. leads) x 6.6 mm (LxW max)"
  rect 1x2.1 smd: 1(-2.285,-3.375) 3(2.285,-3.375)
  rect 5.4x6.2 smd: 4(0,3.375)
  silkscreen extent -3.08,-4.32 3.09,6.38, body extent -3.27,-4.11 3.27,5.83, height 2.39
XCVR_HC-05 [mm]
  rect 1.3x1 smd: 1(-6.35,6.325) 2(-6.35,4.825) 3(-6.35,3.325) 4(-6.35,1.825) 5(-6.35,0.325) 6(-6.35,-1.175) 7(-6.35,-2.675) 8(-6.35,-4.175) 9(-6.35,-5.675) 10(-6.35,-7.175) 11(-6.35,-8.675) 12(-6.35,-10.175) 13(-6.35,-11.675) 22(6.35,-11.675) 23(6.35,-10.175) 24(6.35,-8.675) 25(6.35,-7.175) 26(6.35,-5.675) 27(6.35,-4.175) 28(6.35,-2.675) 29(6.35,-1.175) 30(6.35,0.325) 31(6.35,1.825) 32(6.35,3.325) 33(6.35,4.825) 34(6.35,6.325)
  rect 1x1.3 smd: 14(-5.25,-13.175) 15(-3.75,-13.175) 16(-2.25,-13.175) 17(-0.75,-13.175) 18(0.75,-13.175) 19(2.25,-13.175) 20(3.75,-13.175) 21(5.25,-13.175)
  silkscreen extent -8.1,6.4 -7.9,6.6, body extent -6.5,-13.45 6.5,13.45, height 2.2
ZMC [mil]
  oval 70x90 hole 39.37: 1(-245,0) 2(255,0)
  silkscreen extent -335,-200 340,195, body extent -334,-199 335,199, height 53

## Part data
1k R1 R2 R3 R4 R5 R6 R7 R8 R9 R10 R11 R13 R14 R15 R16 R21 R22 R23 R24 R25 R26 R27 R29: library part RC1206JR-0713RL, "13 Ohms ±5% 0.25W, 1/4W Chip Resistor 1206 (3216 Metric) Moisture Resistant Thick Film", Package="3116 Yageo"
C1 C2 C3 C4 C5 C6 C7 C8 C9 C10 C11 C14 C17 C18: library part C1206C120J5GACTU, "1206 C 12pF Ceramic Multilayer Capacitor, 50 VDC, +125degC, C0G Dielec, +/-5%", Package="3216 KEMET"
C12: "Capacitor"
C13 C15 C16 C19: library part "Cap ELECTROLITIC TOTAL SIZE", "Cap electrolitic radial"
C20: library part Cap-Bipolar, "Bipolar Capacitor", Voltage=100V
D1 D2 D3 D4 D5 D6: library part 1N4148UR-1, "DIODE GEN PURP 75V 200MA DO213AA"
D7 D8 D9 D10 D12 D13 D14 D15: library part "1n4007 SMD M7", "Standard Rectifiers", Manufacturer="DC COMPONENTS"
D11: library part "LED SMD 1206", "SMD 1206 LED"
IC1: "Integrated Circuit", Manufacturer_Name=STMicroelectronics, Mouser Part Number=511-STM32F030K6T6TR
IC2: "Precision 500mA Regulator"
in2 in3: library part "Header 2", "Header, 2-Pin"
L1: library part Inductor, "Inductor"
MOC1: "Opto-Triac"
"NOKIA 1": library part "NOKIA 1202"
P1: "Header, 3-Pin"
pc1: library part PC817XI, "DIP 4pin General Purpose  Photocoupler"
Program: "Header, 4-Pin"
Q1: "45 V, 500 mA NPN general-purpose transistors"
R17 R20: library part "RES DIP PACKAGE", "TOTAL DIP RESISTOR PACK"
R18 R19: library part LR0204F13K3, "13.3 kOhms ±1% 0.25W, 1/4W Through Hole Resistor Axial - Metal Film", Package="Axial TE Connectivity Passive Product"
R28: "13 Ohms ±5% 0.25W, 1/4W Chip Resistor 1206 (3216 Metric) Moisture Resistant Thick Film", Package="3116 Yageo"
ST1 ST2 ST3 ST4: "Switch"
tri1: library part BTA41-600A, "Thyristors, Discretes (diodes, transistors, thyristors ...), Semiconductors and Actives, original, triac, thyristors", Package="TOP-3 STMicroelectronics"
U1: library part AT24C512, "EEPROM"
U2: "Bluetooth to Serial Port Module", Package="Module ITead Studio"
VR1: library part AMS1117
VR2: library part "VARISTOR (VDR)", "VARISTORS", Manufacturer=china-canada-philipina
Zener1: library part "Diode Zener", "Zener Diode", Voltage="3.3 V"

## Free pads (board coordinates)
  round 5 hole 3 slot 5 at 0 deg: ""(-2.984,-20.265) ""(-2.984,39.735) ""(40.016,-20.265) ""(40.016,39.735)

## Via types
v1: diameter 0.813, hole 0.508, Top Layer to Bottom Layer, tented both sides, 76 vias
v2: diameter 1.27, hole 0.711, Top Layer to Bottom Layer, 1 vias
v3: diameter 1, hole 0.5, Top Layer to Bottom Layer, tented both sides, 1 vias
v4: diameter 1, hole 0.5, Top Layer to Bottom Layer, 1 vias

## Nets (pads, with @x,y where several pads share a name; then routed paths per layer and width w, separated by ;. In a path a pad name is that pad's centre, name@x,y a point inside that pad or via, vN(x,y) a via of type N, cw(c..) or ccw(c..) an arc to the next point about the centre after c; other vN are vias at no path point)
9v: C16.1 C17.2 IC2.1 R1.1 R17.2 Zener1.2 | length 63.4
  Top Layer w0.635: C16.1 -1.985,3.394 v1(-0.93,4.449) ; v1(3.094,6.603) v1(3.937,6.603) 27.075,6.603 29.337,8.865 41.129,8.865 Zener1.2
  Bottom Layer w0.5: R17.2 43.523,2.832 43.523,6.471 Zener1.2 43.485,11.95 R1.1
  Bottom Layer w0.635: C16.1 -1.985,3.394 0.59,5.97 1.157,5.97 1.619,6.432 C17.2 ; IC2.1 2.005,6.603 v1(3.094,6.603) v1(3.937,6.603)
adc3.4: IC1.10
amper: C10.2 D2.1 IC1.6 R14.1 | length 17.8
  Bottom Layer w0.3: D2.1 13.638,4.278 12.963,4.953 11.733,4.953 11.557,5.129 R14.1 11.557,13.39 12.963,14.796 IC1.6
backlight: IC1.15 R16.1 | length 6.1
  Bottom Layer w0.5: R16.1 22.775,23.292 23.295,22.772 IC1.15
buzzer: IC1.21 R3.1 | length 3
  Bottom Layer w0.508: IC1.21 27.585,13.196 27.972,12.808 R3.1
GND: "NOKIA 1.1" "NOKIA 1.4" "NOKIA 1.9" "NOKIA 1.10" "NOKIA 1.12" C1.1 C2.2 C3.1 C4.1 C5.1 C6.1 C7.1 C8.1 C9.1 C10.1 C11.1 C13.2 C14.1 C15.2 C16.2 C17.1 C18.1 C19.2 D4.1 D6.1 D9.1 D10.1 D11.1 IC1.16 IC1.31 IC1.32 IC2.4 MOC1.2 P1.3 pc1.3 Program.1 Q1.2 R7.1 R15.1 R24.1 ST1.1 ST2.1 ST3.1 ST4.1 U1.1 U1.2 U1.3 U1.4 U1.7 U2.13 U2.21 U2.22 VR1.1 Zener1.1 | length 59.8
  Top Layer w0.5: ST2.1@21.256,-17.264 20.21,-17.264 v1(20.168,-17.221) 20.168,-13.208 ; ST2.1@21.256,-9.517 20.168,-10.606 20.168,-13.208 ; MOC1.2 27.584,-10.389 24.613,-13.36 20.32,-13.36 20.168,-13.208
  Bottom Layer w0.35: C6.1@15.977,3.478 16.61,3.908 16.745,4.231 17.063,4.726 17.261,4.924 19.185,4.924 19.33,4.924 19.535,5.13 19.535,5.419 19.458,7.415 19.253,7.62 ; IC1.32 18.495,7.825 18.7,7.62 19.253,7.62 ; C5.1 24.462,22.379 24.095,22.012 IC1.16 24.07,17.809 24.07,16.9 23.566,16.396 22.775,16.396 20.665,14.286 v1(20.549,14.286) 20.544,14.28 20.544,13.384 20.538,13.379 20.538,12.407 v1(20.549,12.396) 19.922,11.769 19.922,11.731 19.295,11.104 IC1.31 19.295,7.662 19.253,7.62
  Bottom Layer w0.5: MOC1.2 27.584,-8.082 31.852,-3.814 ; C15.2 37.381,6.24 38.669,6.24 Zener1.1
  other v1: 16.256,-4.826 35.686,-4.547 11.77,-4.166 1.727,-3.861 32.893,-3.683 -1.88,-3.658 0.66,-2.362 45.009,-1.93 43.485,0 19.1,0.756 16.753,1.42 0.66,2.642 7.62,4.039 9.195,7.62 26.873,8.28 3.353,9.195 12.372,9.902 21.638,12.401 20.538,13.341 21.627,13.346 21.638,14.292 29.321,14.416 8.966,17.932 11.466,17.932 12.878,17.932 28.194,17.932 8.966,19.406 -2.057,20.32 2.616,21.082 4.623,21.082 -2.057,21.869 34.123,25.611 30.988,26.111 16.193,26.391 34.123,28.546 41.927,29.159 32.528,30.455 41.859,30.455 1.041,30.561 -3.378,30.734 36.881,31.725 41.927,31.725 41.927,32.995 1.041,34.163 44.171,35.458 -5.123,36.551 34.245,41.478 0.864,42.723 3.073,42.723 5.563,42.723 8.153,42.723 11.466,42.723
INPUT: C3.2 D1.1 IC1.7 R5.2 R7.2 | length 24.5
  Bottom Layer w0.381: R5.2 7.082,25.42 8.26,25.42 8.894,24.786 8.894,21.492 10.3,20.086 13.565,20.086 15.533,18.117 15.533,15.645 15.583,15.596 IC1.7
  Bottom Layer w0.5: R7.2 2.727,27.543 4.893,27.543 D1.1 5.004,25.454 4.904,25.354 7.149,25.354 R5.2 ; C3.2 C3.2@4.725,25.354
L: D12.1 D15.2 in2.1 in3.2 R18.1 | length 59
  Top Layer w0.381: 10.668,-32.08 15.189,-32.08
  Top Layer w0.5: in2.1@22.962,-39.853 in2.1@24.943,-39.827
  Top Layer w1.27: R18.1 10.668,-32.08 ; 15.189,-32.08 in2.1@22.962,-39.853
  Bottom Layer w0.5: D15.2@17.397,-14.455 D15.2
  Bottom Layer w1: R18.1 12.751,-32.08 18.554,-26.277 18.554,-17.667 17.476,-16.589 D15.2 ; D12.1 D15.2@17.397,-14.455
  Bottom Layer w4: in2.1@24.943,-39.827 28.219,-39.853 in3.2
LCD-DN: "NOKIA 1.5" IC1.13 | length 23.9
  Top Layer w0.254: v1(11.466,29.193) 11.466,29.305 12.057,29.896 12.057,34.325
  Bottom Layer w0.4: v1(11.466,29.193) 11.466,28.314 12.39,27.39 12.39,27.009 12.375,26.995 12.375,25.115 13.614,23.876 15.941,23.876 18.608,21.209 21.295,21.209 21.695,20.809 IC1.13
LCD-RST: "NOKIA 1.2" IC1.11 | length 24.7
  Top Layer w0.254: v1(8.894,28.654) 8.894,30.01 9.445,30.561 10.008,30.561 10.284,30.837 10.284,34.325
  Bottom Layer w0.4: v1(8.894,28.654) 8.973,28.575 8.973,28.247 10.975,26.245 10.975,23.696 12.372,22.299 15.166,22.299 17.831,19.634 18.059,19.406 19.861,19.406 20.095,19.171 IC1.11
LCD-SCE: "NOKIA 1.3" IC1.12 | length 24.2
  Top Layer w0.254: v1(10.008,29.193) 10.875,30.06 10.875,34.325
  Bottom Layer w0.4: v1(10.008,29.193) 10.008,28.546 11.675,26.879 11.675,24.389 13.052,23.012 15.533,23.012 18.226,20.32 20.661,20.32 20.895,20.086 IC1.12
LCD-SCLK: "NOKIA 1.6" IC1.14 | length 23.9
  Top Layer w0.254: 12.648,34.325 12.648,29.672 13.36,28.959 13.36,28.233 v1(13.296,28.169)
  Bottom Layer w0.381: v1(13.296,28.169) 13.31,28.155 13.31,25.458 14.028,24.74 16.054,24.74 18.721,22.073 22.149,22.073 22.174,22.098 22.495,21.777 IC1.14
n: C20.2 D13.2 D14.1 in3.1 R19.1 tri1.2 VR2.2 | length 70.8
  Top Layer w1.27: v1(8.755,-15.697) v3(8.755,-16.815) 8.755,-21.811 12.395,-25.451 25.857,-25.451 29.464,-21.844 C20.2 35.255,-21.844 36.035,-21.064 ; VR2.2 36.035,-21.064 ; R19.1 36.805,-15.925 36.035,-16.695 36.035,-21.064
  Bottom Layer w0.5: D13.2 7.24,-14.299 8.611,-14.299 ; v3(8.755,-16.815) v1(8.755,-15.697) 8.696,-15.637 8.696,-14.384 8.611,-14.299 ; D14.1 8.611,-14.299 ; C20.2@30.709,-21.278 C20.2@30.709,-21.234 ; VR2.2 VR2.2@36.035,-26.605
  Bottom Layer w4: in3.1 35.458,-31.999 tri1.2 35.311,-27.623 VR2.2
NetBuzzer1_1: Buzzer1.1 R1.2 | length 6.2
  Bottom Layer w0.5: Buzzer1.1 41.927,15.076 R1.2
NetBuzzer1_2: Buzzer1.2 Q1.3 | length 12.6
  Bottom Layer w0.5: Q1.3 29.752,6.484 29.802,6.534 29.802,6.884 33.325,10.406 Buzzer1.2
NetC2_1: C2.1 P1.1 R2.2 | length 7.3
  Bottom Layer w1: P1.1 -1.551,28.499 -0.4,29.65 R2.2
NetC9_2: C9.2 R13.1 R14.2 | length 10.3
  Bottom Layer w0.508: R13.1@8.755,-4.724 9.053,-4.427 C9.2 9.309,1.105 9.635,1.431 9.635,2.311 10.873,2.311 11.17,2.609 11.17,3.242 11.401,3.473 R14.2
NetC11_2: C11.2 D3.2 D5.2 R13.2 R15.2 | length 16.5
  Bottom Layer w0.35: C11.2 -4.04,-7.821 -2.87,-8.992 3.224,-8.992 3.429,-8.787 D3.2 3.429,-5.746 3.741,-5.435 R15.2 R13.2
NetC12_1: C12.1 R18.2 | length 11
  Bottom Layer w0.5: C12.1 -3.81,-41.276 -3.329,-40.795 ; -2.439,-32.487 -2.403,-32.487 -1.871,-31.955 -1.871,-31.919 -1.635,-31.919 -1.635,-32.071 R18.2
  Bottom Layer w1: -3.329,-40.795 -3.329,-33.377 -2.439,-32.487
NetC12_2: C12.2 D7.1 D10.2 | length 58.6
  Bottom Layer w0.5: D7.1 40.211,-6.477 D10.2
  Bottom Layer w1: C12.2@19.812,-42.103 19.812,-27.457 21.695,-25.574 21.695,-16.481 26.492,-11.684 42.697,-11.684 43.713,-10.668 43.713,-6.579 D10.2
NetC15_1: C15.1 D7.2 D8.2 R17.1 | length 16.9
  Bottom Layer w0.5: C15.1 32.703,3.771 32.703,3.416 33.782,2.337 38.888,2.337 39.345,2.794 R17.1 39.751,-1.546 D7.2@40.052,-1.847 ; D8.2 D7.2@40.052,-1.847 ; D7.2 D7.2@40.052,-1.847
NetC20_1: C20.1 R28.1 R29.1 | length 6.6
  Bottom Layer w0.5: C20.1 C20.1@25.781,-21.599
  Bottom Layer w0.8: R28.1 24.13,-23.495 C20.1 ; C20.1@25.781,-21.599 26.753,-20.627 R29.1
NetD3_1: D3.1 D4.2 L1.1 | length 25.5
  Bottom Layer w0.35: D3.1 3.416,-10.934 1.003,-10.934 D4.2 0.716,-10.946 0.341,-11.321 0.341,-11.596 -0.025,-11.962 -0.025,-17.21 1.23,-18.466 12.771,-18.466 L1.1@14.57,-20.265 ; L1.1@14.978,-20.739 L1.1@15.232,-20.993
NetD5_1: D5.1 D6.2 L1.2 | length 14.3
  Bottom Layer w0.35: D5.1 -1.224,-10.946 -0.849,-11.321 -0.849,-11.596 -0.686,-11.759 -0.686,-18.016 L1.2
NetD8_1: D8.1 D9.2 R20.2 | length 6.4
  Bottom Layer w0.5: D9.2 35.343,-6.47 ; R20.2 35.509,-6.636 35.343,-6.47 ; D8.1 36.906,-6.47 35.343,-6.47
NetD11_2: D11.2 R23.1 | length 3.4
  Bottom Layer w0.381: R23.1 25.885,26.314 D11.2
NetD12_2: D12.2 D14.2 pc1.2 | length 16.7
  Bottom Layer w0.5: D14.2 D12.2 ; pc1.2 14.295,0.584 15.087,-0.209 15.087,-7.722
  Bottom Layer w0.508: D12.2 15.087,-8.055 15.087,-7.722
NetD13_1: D13.1 D15.1 R26.2 | length 21
  Bottom Layer w0.35: R26.2@10.224,-6.684 10.534,-6.374 R26.2 ; D15.1@17.069,-9.5 16.61,-9.5 16.687,-9.422 D15.1 D15.1@17.45,-10.058
  Bottom Layer w0.5: R26.2@10.224,-6.684 9.572,-6.684 7.138,-9.118 D13.1 7.138,-11.253 7.722,-11.836 16.892,-11.836 17.45,-11.278 D15.1@17.45,-10.058
Netin2_2: in2.2 R28.2 tri1.1 VR2.1 | length 15.8
  Bottom Layer w0.5: 27.234,-27.762 28.098,-26.899 VR2.1
  Bottom Layer w0.8: R28.2@24.289,-27.762 27.234,-27.762
  Bottom Layer w4: in2.2 29.405,-32.233 tri1.1 28.389,-30.455 VR2.1
NetMOC1_1: MOC1.1 R27.1 | length 4.4
  Bottom Layer w0.5: R27.1 23.839,-7.989 MOC1.1
  Bottom Layer w1: MOC1.1 MOC1.1@25.044,-8.995
NetMOC1_4: MOC1.4 tri1.3 | length 19.9
  Bottom Layer w1: MOC1.4 30.124,-16.852 30.402,-17.13 31.074,-17.13 40.836,-26.891 tri1.3
NetMOC1_6: MOC1.6 R29.2 | length 2.3
  Bottom Layer w0.8: R29.2@23.931,-18.636 23.931,-17.929 MOC1.6
"NetNOKIA 1_11": "NOKIA 1.11" R16.2 | length 14.9
  Top Layer w0.35: 15.602,34.325 15.602,28.128 15.404,27.929 15.404,24.3 16.14,23.564 17.32,23.564 17.428,23.672 v1(18.732,23.672)
  Bottom Layer w0.35: v1(18.732,23.672) R16.2
Netpc1_1: pc1.1 R26.1 | length 4.9
  Bottom Layer w0.3: pc1.1 12.04,-1.956 pc1.1@12.243,-2.159 ; R26.1 13.494,-5.105
  Bottom Layer w0.5: pc1.1@12.243,-2.159 13.494,-3.41 13.494,-5.105
NetQ1_1: Q1.1 R3.2 | length 7.9
  Bottom Layer w0.3: Q1.1 26.119,5.534 25.508,6.145 25.508,8.619 26.738,9.848 R3.2
NetR19_2: R19.2 R20.1 | length 5.9
  Top Layer w0.5: R20.1 R20.1@35.686,-13.513 ; R19.2@39.674,-9.525 R19.2
  Top Layer w0.762: R20.1@35.686,-13.513 R19.2@39.674,-9.525
NetR21_1: R21.1 U2.2 | length 16.6
  Bottom Layer w0.35: R21.1 1.981,40.462 2.642,39.802 15.583,39.802 16.245,40.464 U2.2
NetR22_1: R22.1 U2.1 | length 11.3
  Bottom Layer w0.35: R22.1 4.901,41.282 5.721,40.462 14.215,40.462 14.42,40.667 14.42,41.153 U2.1
NetR23_2: R23.2 U2.31 | length 2.6
  Bottom Layer w0.381: U2.31 19.245,27.039 19.59,26.694 R23.2
NetR24_2: R24.2 U2.34 | length 2.6
  Bottom Layer w0.381: R24.2 14.621,26.439 14.621,28.654 U2.34
RESET: 1k.1 C8.2 IC1.4 | length 5.4
  Bottom Layer w0.3: 1k.1 13.614,13.196 13.614,13.321 13.739,13.196 IC1.4
rx: IC1.9 R22.2 | length 29.3
  Bottom Layer w0.35: R22.2 4.521,37.421 4.726,37.216 5.994,37.216 7.469,35.741 7.469,28.442 10.3,25.611 10.3,22.974 11.836,21.438 14.621,21.438 17.457,18.602 17.457,17.834 IC1.9
SCL: IC1.18 R4.2 U1.6 | length 24.3
  Bottom Layer w0.4: IC1.18 27.483,15.596 29.175,17.288 29.175,22.874 32.995,26.694 R4.2@36.068,26.694 ; R4.2 R4.2@36.068,26.694 ; U1.6@38.557,30.531 36.881,30.531 36.068,29.718 R4.2@36.068,26.694
SDA: IC1.19 R6.2 U1.5 | length 24.9
  Bottom Layer w0.4: IC1.19 27.846,14.796 29.875,16.824 29.875,22.125 32.312,24.562 R6.2 37.47,28.765 37.852,29.146 38.912,29.146 U1.5
Sens: C4.2 P1.2 R5.1 | length 11.9
  Bottom Layer w0.5: P1.2 -1.253,25.959 -0.646,25.351 C4.2 2.261,25.072 2.261,24.169 2.553,23.876 6.754,23.876 7.047,23.583 R5.1
sw1: IC1.30 R8.1 ST1.2 | length 30.2
  Top Layer w0.3: ST1.2@0.037,0 7.784,0 7.784,2.263 7.959,2.438 18.475,2.438 v1(19.594,3.557)
  Bottom Layer w0.3: R8.1 19.594,3.549 20.034,3.549 20.122,3.637 20.21,3.725 20.21,7.731 20.095,7.845 IC1.30
SW2: IC1.27 R9.1 ST2.2 | length 38.3
  Top Layer w0.5: ST2.2@16.43,-17.264 16.43,-7.344 16.967,-6.807 25.171,-6.807 25.808,-6.17 v1(25.808,1.42)
  Bottom Layer w0.5: IC1.27 22.495,3.978 24.903,1.571 25.658,1.571 25.959,1.27 R9.1@25.959,0.268
sw3: IC1.25 R10.1 ST3.2 | length 23.5
  Top Layer w0.5: v1(29.979,2.126) 29.979,0.35 29.629,0 29.514,0 ST3.2@37.261,0
  Bottom Layer w0.5: IC1.25 24.095,5.42 26.187,3.327 28.778,3.327 v1(29.979,2.126) 30.778,1.328 R10.1@30.778,0.258
SW4: IC1.26 R11.1 ST4.2 | length 28
  Top Layer w0.3: ST4.2@14.757,0 15.207,-0.45 15.774,-0.45 15.783,-0.459 21.645,-0.459 22.104,0 22.504,0 22.723,0.219 22.723,0.874 24.922,3.073 26.772,3.073 v1(28.194,1.651)
  Bottom Layer w0.381: IC1.26 23.295,7.62 23.295,4.619 25.603,2.311 27.504,2.311 28.245,1.571 R11.1@28.245,0.584
TCK: IC1.24 Program.3 | length 27.6
  Bottom Layer w0.381: IC1.24 30.542,10.796 31.566,11.82 31.566,20.897 33.048,22.379 42.473,22.379 Program.3@42.829,22.736
TMS: IC1.23 Program.4 | length 29.4
  Bottom Layer w0.381: IC1.23 30.166,11.596 30.778,12.208 30.778,21.31 32.528,23.06 41.636,23.06 41.859,23.283 41.859,24.821 42.082,25.044 Program.4@43.143,25.044
triakPulse: IC1.29 R27.2 | length 17
  Bottom Layer w0.3: R27.2@20.661,-5.029 18.237,-2.606 18.237,1.628 18.413,1.803 19.357,1.803 20.895,3.342 IC1.29
tx: IC1.8 R21.2 | length 31.3
  Bottom Layer w0.381: R21.2 2.261,38.042 2.261,37.363 3.073,36.551 5.638,36.551 6.658,35.53 6.658,28.312 9.635,25.335 9.635,22.302 11.17,20.767 14.017,20.767 16.667,18.117 16.667,17.683 17.057,17.292 IC1.8
VCC-3.3v: 1k.2 "NOKIA 1.7" "NOKIA 1.8" C1.2 C5.2 C6.2 C7.2 C13.1 C14.2 D1.2 D2.2 IC1.1 IC1.5 IC1.17 Program.2 R4.1 R6.1 R8.2 R9.2 R10.2 R11.2 R25.2 U1.8 U2.12 VR1.2 VR1.4 | length 276.9
  Top Layer w0.229: v1(5.029,31.852) 5.029,29.083 6.959,27.153 14.384,27.153 ; 13.238,34.325 13.237,34.323 13.237,31.064 13.829,30.472 13.829,34.325
  Top Layer w0.5: v1(18.771,11.769) 3.057,11.769 0.889,9.601 0.889,5.588 1.676,4.801 7.029,4.801 7.224,4.995 28.388,4.995 30.301,3.083 30.375,3.083 30.537,2.921 31.648,2.921 33.122,1.448 38.905,1.448 39.109,1.244 39.142,1.244 39.903,0.483 39.903,-0.94 38.481,-2.362 28.143,-2.362 27.127,-3.378 v4(27.127,-4.242) ; 27.457,21.666 27.457,39.091 v2(31.267,42.901)
  Top Layer w0.508: 40.488,23.851 40.488,20.491 40.785,20.193 Program.2@43.226,20.193 ; v1(40.488,26.391) v1(40.488,27.229)
  Top Layer w0.762: C13.1 12.497,15.621 ; 13.829,30.472 14.384,29.918 14.384,27.153 14.384,21.666 ; v1(18.771,11.769) 18.771,11.783 18.821,11.833 v1(18.821,13.996) 17.196,15.621 ; v1(23.566,15.338) 23.557,15.348 22.019,15.348 21.746,15.621 17.196,15.621 ; v1(40.488,26.391) 40.488,23.851 38.303,21.666 27.457,21.666 14.384,21.666 ; 12.497,15.621 17.196,15.621 ; 12.497,15.621 14.384,17.508 14.384,21.666
  Bottom Layer w0.229: D1.2 5.029,30.758 v1(5.029,31.852) 5.029,34.11 C7.2
  Bottom Layer w0.35: 1k.2 13.924,8.812 14.883,8.812 15.697,9.626 ; C6.2@15.697,6.343 15.697,9.626 ; IC1.5 v1(18.821,13.996) ; v1(18.771,11.769) 18.771,11.499 18.093,10.821 17.082,10.821 IC1.1 15.902,10.796 15.697,10.591 15.697,9.626 ; v1@23.566,15.316 v1(23.566,15.338) 24.599,16.371 25.508,16.371 IC1.17 25.536,16.399 26.745,16.399 27.302,16.957 27.302,19.102 C5.2
  Bottom Layer w0.5: v4(27.127,-4.242) 27.584,-4.242 27.927,-3.899 27.927,-3.127 R11.2 ; U2.12 31.245,42.861 v2@31.267,42.884
  Bottom Layer w0.508: U1.8 40.894,32.995 ; R4.1 39.097,26.352 39.201,26.248 v1@40.437,26.248 ; C14.2 39.851,35.001 40.894,33.958 40.894,32.995 ; R6.1 40.437,24.568 v1@40.437,26.248 ; v1@40.437,26.248 40.437,28.702 40.894,29.159 40.894,32.995
  Bottom Layer w0.762: C13.1 -1.88,15.367 -0.127,15.367 1.016,14.224 VR1.4 ; C1.2 4.723,16.302 3.094,14.674 VR1.4 ; VR1.2 VR1.4 ; 1k.2 13.626,8.49 13.626,6.615 D2.2 ; C6.2@16.245,6.428 16.285,6.468 18.339,6.468 R8.2@18.379,6.508 ; R25.2@23.8,-2.579 24.18,-2.579 24.303,-2.702 R9.2 R11.2 R10.2@30.778,-2.702
  other v1: -0.93,15.621
VCC_5V: C18.2 C19.1 IC2.3 R2.1 VR1.3 | length 50.2
  Top Layer w1: C19.1 -2.052,9.902 v1(-0.542,9.902)
  Bottom Layer w0.635: -4.445,9.677 -4.623,9.855 -4.623,34.271 -4.251,34.643 -3.527,34.643 -3.36,34.811 R2.1
  Bottom Layer w1: -4.445,9.677 -2.277,9.677 C19.1 -2.052,9.902 v1(-0.542,9.902) -0.295,9.902 1.132,11.328 6.422,11.328 7.017,11.924 9.068,11.924 C18.2 7.062,9.095 6.476,8.509 IC2.3
ZeroCross: IC1.28 pc1.4 R25.1 | length 14.5
  Bottom Layer w0.5: pc1.4 21.344,-1.544 22.818,-1.544 23.8,-0.562 23.8,0.381 23.42,0.381 23.185,0.616 23.185,1.606 21.695,3.095 IC1.28
pads on no net: D1.0 D2.0 D3.0 D4.0 D5.0 D6.0 IC1.2 IC1.3 IC1.20 IC1.22 MOC1.3 MOC1.5 U2.3 U2.4 U2.5 U2.6 U2.7 U2.8 U2.9 U2.10 U2.11 U2.14 U2.15 U2.16 U2.17 U2.18 U2.19 U2.20 U2.23 U2.24 U2.25 U2.26 U2.27 U2.28 U2.29 U2.30 U2.32 U2.33

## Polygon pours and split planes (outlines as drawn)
GND on Top Layer "NONET_L-01_P-001" (solid, remove dead copper, pour order 1): 45.898,43.688 45.898,-7.849 32.944,-7.849 31.953,-8.839 31.953,-14.072 24.663,-14.072 23.673,-15.926 23.673,-19.462 18.502,-19.462 10.084,-19.462 10.084,-13.538 11.659,-13.538 -5.715,-13.538 -5.715,43.637 -5.664,43.688 45.72,43.688
GND on Bottom Layer "NONET_L-01_P-001" (solid, remove dead copper, pour order 0): 45.517,-4.115 45.466,-4.166 31.566,-4.166 31.566,-9.956 30.854,-10.668 20,-10.668 19.535,-10.202 19.535,-6.25 18.339,-5.055 16.745,-5.055 16.745,0.756 15.374,2.126 10.992,2.126 10.008,1.142 10.008,-3.748 9.068,-4.688 9.068,-5.622 8.316,-6.374 5.437,-6.374 4.928,-6.883 4.928,-16.891 5.965,-17.929 15.903,-17.929 17.245,-19.271 17.245,-24.03 15.35,-25.925 0.627,-25.925 -0.229,-25.07 -0.025,-24.867 -0.025,-18.683 -1.64,-17.069 -5.41,-17.069 -5.918,-16.561 -5.918,43.51 -6.02,43.612 -5.994,43.637 45.847,43.637

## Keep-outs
Keep-Out Layer:
  lines w0.254: -6.02,-43.967 45.796,-43.967 45.796,43.459 45.695,43.561 -6.02,43.561 -6.02,-43.967

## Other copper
Top Layer:
  rectangle net VCC-3.3v: 13.073,29.907 14.002,37.49
Bottom Layer:
  rectangle net GND: 1.016,-2.702 7.366,2.572
  rectangle net GND: 2.116,-3.658 6.476,3.503
  pour cut-out: 6.909,-18.11 6.274,-17.475 -6.858,-17.475
  pour cut-out: 38.966,34.117 38.966,33.632 38.964,33.63 39.091,33.503 40.157,33.503 40.157,33.839 39.88,34.117
  pour cut-out: 31.598,-10.338 31.547,-10.287 19.338,-10.287 19.338,-10.922 19.389,-10.973 31.674,-10.973 31.674,-10.4 31.56,-10.287

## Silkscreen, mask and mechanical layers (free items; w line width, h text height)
Bottom Overlay:
  drawing of 7 lines, arcs and shapes, not listed
  text "Serial : AR-L0202" at 34.577,41.642 h1
  text "+" at -0.062,37.084 h1 r270
  text "Don't Touch" at 56.218,-27.381 h1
